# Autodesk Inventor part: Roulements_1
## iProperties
Created: 2002-06
Part Number: Roulements_1
Material: Par défaut
Document SubType Name: Modélisation
Designer: REVEST Pierre
Control State: 0
Master: False
Checked Out: False
Shininess: 20.0
Length Units: 11269
Angle Units: 11279
Time Units: 11290
Mass Units: 11283
Length Display Precision: 3
Angle Display Precision: 2
Density: 0.0
Volumn: 0.0
Area: 0.0
PropertySet Name: Model Information
Author: REVEST Pierre
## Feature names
1. Base1
